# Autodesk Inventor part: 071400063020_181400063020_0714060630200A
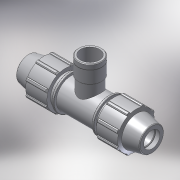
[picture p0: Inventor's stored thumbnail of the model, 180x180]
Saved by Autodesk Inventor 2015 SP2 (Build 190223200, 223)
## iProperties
Created: 2017-02
Part Number: 071400063020_181400063020_0714060630200A
Material: PVC-Piping
Description: PLASSON TEE WITH THREADED FEMALE OFFTAKE 63-2"-63
Document SubType Name: Modeling
Designer: KIM
Mass: 92.6774 g
Surface Area: 199.44 cm^2
Volume: 66.1981 cm^3
Density: 1.4 g/cm^3
Appearance: Smooth - White
Author: KIM
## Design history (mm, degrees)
derived "07140.ipt"
feature "Solid1::07140.ipt"
feature "Solid2::07140.ipt"
tag "TaggingFeature1"
body "Solid1"
other parameters: "d2" = 63, "d4" = 11.33333, "d5" = 32.64, "d7" = 113, "d11" = 4.53333, "d13" = 120 deg, "d14" = 81.9, "d15" = 12 deg, "d16" = 98.31, "d18" = 3.15, "d19" = 35 deg, "d20" = 17.5 deg, "d21" = 105.09, "d23" = 0, "d25" = 360 deg, "d27" = 2.26, "d33" = 1.26, "d42" = 48.96, "d43" = 3.39, "d46" = 1.89, "d68" = 8.16, "d72" = 95, "d76" = 56.656, "d80" = 1.69968, "d91" = 84.75, "d95" = 56.7, "d115" = 70.82, "d116" = 135 deg, "d117" = 65.1544, "d118" = 272, "d119" = 56.7, "d121" = 0, "d122" = 51.03, "d124" = 0, "d128" = 0, "d129" = 6.3, "d130" = 9, "d131" = 0.3, "d132" = 0.3, "d133" = 70.82, "d_" = 63, "E_" = 113, "A_" = 95, "Rp_" = 56.656, "H_" = 272
